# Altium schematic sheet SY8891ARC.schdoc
size 127 x 101 mm
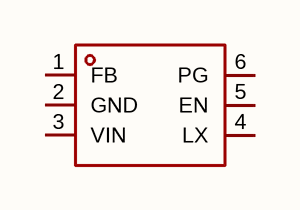
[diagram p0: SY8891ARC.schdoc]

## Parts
Q?  sy8891arc  [SOT-563-6_L1.6-W1.2-P0.5-LS1.6-BL]  (value not drawn)

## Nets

Not connected (* = marked no-connect by the designer): Q? 1(FB) 2(GND) 3(VIN) 4(LX) 5(EN) 6(PG)

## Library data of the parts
Q? = sy8891arc: 功能类型:降压型;工作电压:2.5V~5.5V;输出电压:-;输出电流:1A;输出类型:可调;; Manufacturer: Silergy(矽力杰); AddInBom: yes; ModelId: 6c48915c55ca481897faee5dfab5b527; ModelTransform: 62.992,62.992,0,0,0,0,0,0,0; Function: 降压型; Output Current: 1A; Frequency - Switching: 1.5MHz; Synchronous Rectifier: 是; Number of Outputs: 1; Topology: 降压式; Quiescent Current: 55uA; Switch tube (built-in/external): 内置; Output Type: 可调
